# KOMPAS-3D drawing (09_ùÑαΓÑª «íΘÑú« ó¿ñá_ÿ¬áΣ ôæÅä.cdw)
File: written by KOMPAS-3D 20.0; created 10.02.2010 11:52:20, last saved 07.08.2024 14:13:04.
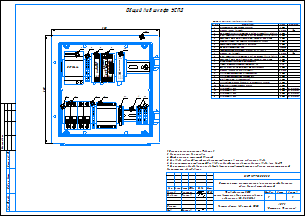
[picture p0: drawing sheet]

Sheet 1: A3, landscape

Document properties: Автор: Силов Дмитрий Дмитриевич; Организация: ЗАО ИТФ "Системы и Технологии"; Разработал: Воронина; Проверил: Тарасов; Утвердил: Шмончев; Полное имя файла: \\s-tech\Depts\Отдел_ПКО\Сотрудники\Голдина\MES X.Y.Z Шкаф компактный распределительный 3D\MES 30.30.15 Шкаф компактный распределительный.a3d; Масса: 5.55816; Наименование: MES 30.20.15 Шкаф компактный распределительный

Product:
- Part/product: (unnamed)
  - Component: Рейка  | designation 123  | qty 4  | pos. 1  | Раздел спецификации: Детали

Table, sheet 1:
  111111111
Title block, sheet 2: Наименование: Шкаф учета настненный для установки / счетчика; designation: ВЛСТ 1277.02.000 В0; Материал: Общий вид шкафа учета; scale: 1:4; sheet number: 1; organisation: АО ГК / "Системы и Технологии"; Форматы листов документа: A3; stored path: Z:\!Оборудование СТ\Шкафы учета\Паспорта\На соглосовании\ВЛСТ 225.11.000\КД\СБ.cdw; cell 302: Система учета электроэнергии (с организацией удаленного / сбора данных) потребителей; cell 303: Типовой проект ИСУЭ / многоквартирного дома с использованием / радиоканала (F2/868 МГц); cell 304: Чертеж общего вида шкафа УСПД; cell 320: Р

Referenced files in \\Helios\отдел_пко\Общая папка Компас\_Addons\Signatures\: Signatures.lfr|Тарасов, Signatures.lfr, Signatures.lfr|Шмончев
Referenced files in C:\Program Files\ASCON\KOMPAS-3D V13\Libs\_Addons\Signatures\: Signatures.lfr
Referenced files: qlkzkl.frw, hsklda.frw, jndvba.frw
Referenced files in Y:\Общая папка Компас\_Addons\Signatures\: Signatures.lfr|Голдина, Signatures.lfr
Referenced files in \\s-tech\depts\Отдел_ПКО\Сотрудники\Голдина\: Devices GK.lfr
Referenced files in \\s-tech\Depts\Отдел_ПКО\Сотрудники\Голдина\MES X.Y.Z Шкаф компактный распределительный 3D\: Винт для петли 202-0606 М6х6_5.m3d, Шайба Skiffy 003 0600 000 01_6.m3d, Гайка оц. М8 DIN 934.m3d, MES 30.20.15 Корпус_MES 30.30.15 00.000‘Ѓ Љ®аЇгб.m3d, Гайка оц. с фланцем, рифленая М8 DIN 6923_Hexagon Flange Nut DIN 6923 - M8 - C_4.m3d, MES 30.20 Дверь_MES 30.30 02.000‘Ѓ „ўҐам.m3d
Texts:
  Тарасов
  Шмончев
  Голдина
  Normal
  Centerline
  Outline
  Общий вид шкафа УСПД
  Таблица 1 - Перечень основного оборудования
  № поз.
  Колич.
  Электронный переключатель фаз ПЭФ-301
  HMT.2/2+2/PT(Ex)i, торцевой изолятор синий для НММ.2/2+2
  HMM.2/2+2(Ex)i, проходной зажим 2,5 кв.мм синий 2 ввод/2 вывода
  Клеммник ("N") в составе:
  Автоматический выключатель ВА47-29 2Р 6А х-ка С
  BTO, Торцевой фиксатор 5мм
  Интеллектуальный контроллер SM160-02M
  RF-формирователь Link ST200.F2-K1 ВЛСТ 339.10.000-K1
  HMM.2/2+2GR(Ex), проходной зажим 2,5 кв.мм серый 2 ввод/2 вывода
  Клеммник ("=24В") в составе:
  Блок питания 30 Вт (ВЛСТ 1000.10.002)
  Профиль металлический DIN-рейка TS 35/7.5
  Шина РЕ "земля" на DIN-изоляторе ШНИ-6х9-6-Д-Ж
  Клеммник ("RS-485 сч. ВРУ") в составе:
  Проходной клеммный зажим серый ZHM500GR
  Проходной клеммный зажим синий ZHI500
  Торцевой изолятор серый ZHM501GR
  Преобразователь линии RS-485/CAN (ВЛСТ 217.00.000-04)
  Шкаф распределительный MES 30.30.15
  ХТ1
  QF1, QF2
  ХТ2
  Кабельный ввод М16
  Кабельный ввод М12
  Кабельный ввод М25
  Кабельный ввод М32
  не показана
  1. Позиции указаны согласно Таблице 1.
  3. Размеры указаны для справок.
  4. Шкаф показан с открытой дверцей.
  5. Для ввода кабелей в шкаф просверлить отверстия в панели кабельного ввода.
  6. Для герметизации отверстий для ввода кабелей использовать кабельные вводы (поз. 14-17).
  7. При монтаже оборудования руководствоваться соответствующими разделами эксплуатационной
  документации оборудования.
  Пит.
  Тест
  Сброс
  Реж.
  Раб.
  SIM1
  SIM2
  SM160
  DSP30-24
  USB
  Link ST200
  Акт.
  Лицевая панель.png
  POLYLINE_STYLE_0.18_RGB_0_0_0
  POLYLINE_STYLE_0.25_RGB_0_0_0
  Стили документа
  Рейка
  2D_Doc-graphic.lyt,1.000000-0-170951471925
  2D_Doc-graphic.lyt,1.000000-0-170951472025
  2D_Doc-graphic.lyt,1.000000-0-170951472125
  2D_Doc-graphic.lyt,1.000000-0-170951472225
  Винт для петли 202-0606 М6х6
  Шайба Skiffy 003 0600 000 01
  Гайка оц. М8 DIN 934
  MES 30.20.15 Корпус_MES 30.30.15 00.000‘Ѓ Љ®аЇгб
  Гайка оц. с фланцем, рифленая М8 DIN 6923_Hexagon Flange Nut DIN 6923 - M8 - C
  MES 30.20 Дверь_MES 30.30 02.000‘Ѓ „ўҐам
  ANSI37
  Разраб.
  Н.контр.
  Утв.
  Общий вид
  шкафа учёта
  Воронина
  03 Рабочие чертежи основного комплекта. ГОСТ 21.101-97 Ф3
Dimensions and other numbers on the sheet: 3с5; 3,0; 5и0; 3и3; 35; 6; 8; 7; 5; 4; 3; 2; 1; 9; 10; 11; 12; 13; 1 шт.; 1 компл.; 2 шт.; 13 шт.; 0,6 м; 2 компл.; 15; 14; 16; 17; 3 шт.; 300; 4хRS-485; 123; 18; 19; 20; 21; 22; 23; 24; 25; 26; 27; 1:4; 03.23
